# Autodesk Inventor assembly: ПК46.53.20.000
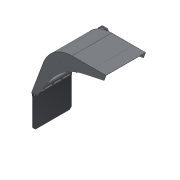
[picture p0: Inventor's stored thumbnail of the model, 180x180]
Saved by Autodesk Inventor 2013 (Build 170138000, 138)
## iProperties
Created: 2005-03
Part Number: ПК46.53.20.000
Document SubType Name: Assembly
Designer: HKostja
Manufacturer: Standard
Standards Organization: Custom
Description: Крыло переднее
Author: HKostja
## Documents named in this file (12)
- C:\Product Design Suite 2013 Test Drive\Dynamic Simulation\Workspace\Assy, Chassis, Front\PK46.53.20.000.iam
- C:\Product Design Suite 2013 Test Drive\Dynamic Simulation\Workspace\Assy, Chassis, Front\PK46.53.20.001.ipt
- C:\Product Design Suite 2013 Test Drive\Dynamic Simulation\Workspace\Assy, Chassis, Front\PK46.53.20.001-01.ipt
- C:\Product Design Suite 2013 Test Drive\Dynamic Simulation\Workspace\Assy, Chassis, Front\PK46.53.20.002.ipt
- C:\Product Design Suite 2013 Test Drive\Dynamic Simulation\Workspace\Assy, Chassis, Front\PK46.53.20.004.ipt
- C:\Product Design Suite 2013 Test Drive\Dynamic Simulation\Workspace\Assy, Chassis, Front\PK46.53.20.003.ipt
- C:\Product Design Suite 2013 Test Drive\Dynamic Simulation\Workspace\Assy, Chassis, Front\PK46.53.20.005.ipt
- C:\Product Design Suite 2013 Test Drive\Dynamic Simulation\Workspace\Assy, Chassis, Front\PK46.53.20.006.ipt
- C:\Product Design Suite 2013 Test Drive\Dynamic Simulation\Workspace\Assy, Chassis, Front\M10-6H.5.019(S16).ipt
- C:\Product Design Suite 2013 Test Drive\Dynamic Simulation\Workspace\Assy, Chassis, Front\10.65G.019.ipt
- C:\Product Design Suite 2013 Test Drive\Dynamic Simulation\Workspace\Assy, Chassis, Front\M10-6gx30.58.019(S16).ipt
- C:\Product Design Suite 2013 Test Drive\Dynamic Simulation\Workspace\Assy, Chassis, Front\PK46.53.20.007.ipt
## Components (26 placed, 11 different names)
1. PK46.53.20.001:1 — Заподлицо:2, Совмещение:9, Совмещение:10, Совмещение:8, Совмещение:14, Совмещение:15
2. PK46.53.20.001-01:1 — Совмещение:7, Заподлицо:3, Совмещение:13, Совмещение:16, Совмещение:17, Совмещение:22, Совмещение:26
3. PK46.53.20.002:1 — Совмещение:7, Заподлицо:2, Совмещение:9, Заподлицо:3, Совмещение:10, Совмещение:8, Совмещение:13, Угол:1, Угол:2, Вставка:3, Совмещение:20, Вставка:20, Вставка:21, Вставка:22, Вставка:23, Вставка:24, Совмещение:28, Совмещение:29
4. PK46.53.20.003:1 — Совмещение:14, Совмещение:16, Вставка:2, Совмещение:18, Касательность:1
5. PK46.53.20.003:2 — Совмещение:15, Совмещение:17, Вставка:1, Совмещение:19, Угол:1, Совмещение:23, Совмещение:25
6. PK46.53.20.007:3 — Вставка:2, Совмещение:18, Угол:2
7. PK46.53.20.007:2 — Вставка:1, Совмещение:19
8. PK46.53.20.004:1 — Совмещение:21, Вставка:4, Вставка:10, Вставка:11, Вставка:12, Вставка:13, Вставка:14
9. PK46.53.20.005:1 — Вставка:3, Совмещение:20, Совмещение:21, Вставка:4
10. M10-6gx30.58.019(S16):5 — Вставка:24, Заподлицо:4
11. M10-6gx30.58.019(S16):4 — Вставка:23, Заподлицо:4, Заподлицо:5
12. M10-6gx30.58.019(S16):3 — Вставка:22, Заподлицо:5, Заподлицо:6
13. M10-6gx30.58.019(S16):2 — Вставка:21, Заподлицо:6, Заподлицо:7
14. M10-6gx30.58.019(S16):1 — Вставка:20, Заподлицо:7
15. M10-6H.5.019(S16):1 — Вставка:16, Заподлицо:8, Заподлицо:9
16. M10-6H.5.019(S16):2 — Вставка:17, Заподлицо:9, Заподлицо:10
17. M10-6H.5.019(S16):3 — Вставка:18, Заподлицо:10, Заподлицо:11
18. M10-6H.5.019(S16):4 — Вставка:19, Заподлицо:11
19. M10-6H.5.019(S16):5 — Вставка:15, Заподлицо:8
20. 10.65G.019:1 — Вставка:10, Вставка:19
21. 10.65G.019:2 — Вставка:11, Вставка:18
22. 10.65G.019:3 — Вставка:12, Вставка:17
23. 10.65G.019:4 — Вставка:13, Вставка:15
24. 10.65G.019:5 — Вставка:14, Вставка:16
25. PK46.53.20.006:1 — Совмещение:22, Совмещение:23, Совмещение:25
26. PK46.53.20.006:2 — Совмещение:26, Совмещение:28, Касательность:1, Совмещение:29
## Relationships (51: Mate 19, Insert 19, Flush 10, Angle 2, Tangent 1)
- Совмещение:7 [Mate]: PK46.53.20.001-01:1 ↔ PK46.53.20.002:1
- Заподлицо:2 [Flush]: PK46.53.20.001:1 ↔ PK46.53.20.002:1
- Совмещение:9 [Mate]: PK46.53.20.001:1 ↔ PK46.53.20.002:1
- Заподлицо:3 [Flush]: PK46.53.20.001-01:1 ↔ PK46.53.20.002:1
- Совмещение:10 [Mate]: PK46.53.20.001:1 ↔ PK46.53.20.002:1
- Совмещение:8 [Mate]: PK46.53.20.001:1 ↔ PK46.53.20.002:1
- Совмещение:13 [Mate]: PK46.53.20.001-01:1 ↔ PK46.53.20.002:1
- Совмещение:14 [Mate]: PK46.53.20.001:1 ↔ PK46.53.20.003:1
- Совмещение:15 [Mate]: PK46.53.20.001:1 ↔ PK46.53.20.003:2
- Совмещение:16 [Mate]: PK46.53.20.001-01:1 ↔ PK46.53.20.003:1
- Совмещение:17 [Mate]: PK46.53.20.001-01:1 ↔ PK46.53.20.003:2
- Вставка:1 [Insert]: PK46.53.20.003:2 ↔ PK46.53.20.007:2
- Вставка:2 [Insert]: PK46.53.20.003:1 ↔ PK46.53.20.007:3
- Совмещение:18 [Mate]: PK46.53.20.003:1 ↔ PK46.53.20.007:3
- Совмещение:19 [Mate]: PK46.53.20.003:2 ↔ PK46.53.20.007:2
- Угол:1 [Angle]: PK46.53.20.002:1 ↔ PK46.53.20.003:2
- Угол:2 [Angle]: PK46.53.20.002:1 ↔ PK46.53.20.007:3
- Вставка:3 [Insert]: PK46.53.20.002:1 ↔ PK46.53.20.005:1
- Совмещение:20 [Mate]: PK46.53.20.002:1 ↔ PK46.53.20.005:1
- Совмещение:21 [Mate]: PK46.53.20.004:1 ↔ PK46.53.20.005:1
- Вставка:4 [Insert]: PK46.53.20.004:1 ↔ PK46.53.20.005:1
- Вставка:10 [Insert]: PK46.53.20.004:1 ↔ 10.65G.019:1
- Вставка:11 [Insert]: PK46.53.20.004:1 ↔ 10.65G.019:2
- Вставка:12 [Insert]: PK46.53.20.004:1 ↔ 10.65G.019:3
- Вставка:13 [Insert]: PK46.53.20.004:1 ↔ 10.65G.019:4
- Вставка:14 [Insert]: PK46.53.20.004:1 ↔ 10.65G.019:5
- Вставка:15 [Insert]: M10-6H.5.019(S16):5 ↔ 10.65G.019:4
- Вставка:16 [Insert]: M10-6H.5.019(S16):1 ↔ 10.65G.019:5
- Вставка:17 [Insert]: M10-6H.5.019(S16):2 ↔ 10.65G.019:3
- Вставка:18 [Insert]: M10-6H.5.019(S16):3 ↔ 10.65G.019:2
- Вставка:19 [Insert]: M10-6H.5.019(S16):4 ↔ 10.65G.019:1
- Вставка:20 [Insert]: PK46.53.20.002:1 ↔ M10-6gx30.58.019(S16):1
- Вставка:21 [Insert]: PK46.53.20.002:1 ↔ M10-6gx30.58.019(S16):2
- Вставка:22 [Insert]: PK46.53.20.002:1 ↔ M10-6gx30.58.019(S16):3
- Вставка:23 [Insert]: PK46.53.20.002:1 ↔ M10-6gx30.58.019(S16):4
- Вставка:24 [Insert]: PK46.53.20.002:1 ↔ M10-6gx30.58.019(S16):5
- Заподлицо:4 [Flush]: M10-6gx30.58.019(S16):5 ↔ M10-6gx30.58.019(S16):4
- Заподлицо:5 [Flush]: M10-6gx30.58.019(S16):4 ↔ M10-6gx30.58.019(S16):3
- Заподлицо:6 [Flush]: M10-6gx30.58.019(S16):3 ↔ M10-6gx30.58.019(S16):2
- Заподлицо:7 [Flush]: M10-6gx30.58.019(S16):2 ↔ M10-6gx30.58.019(S16):1
- Заподлицо:8 [Flush]: M10-6H.5.019(S16):1 ↔ M10-6H.5.019(S16):5
- Заподлицо:9 [Flush]: M10-6H.5.019(S16):1 ↔ M10-6H.5.019(S16):2
- Заподлицо:10 [Flush]: M10-6H.5.019(S16):2 ↔ M10-6H.5.019(S16):3
- Заподлицо:11 [Flush]: M10-6H.5.019(S16):3 ↔ M10-6H.5.019(S16):4
- Совмещение:22 [Mate]: PK46.53.20.001-01:1 ↔ PK46.53.20.006:1
- Совмещение:23 [Mate]: PK46.53.20.003:2 ↔ PK46.53.20.006:1
- Совмещение:25 [Mate]: PK46.53.20.003:2 ↔ PK46.53.20.006:1
- Совмещение:26 [Mate]: PK46.53.20.001-01:1 ↔ PK46.53.20.006:2
- Совмещение:28 [Mate]: PK46.53.20.002:1 ↔ PK46.53.20.006:2
- Касательность:1 [Tangent]: PK46.53.20.003:1 ↔ PK46.53.20.006:2
- Совмещение:29 [Mate]: PK46.53.20.002:1 ↔ PK46.53.20.006:2
